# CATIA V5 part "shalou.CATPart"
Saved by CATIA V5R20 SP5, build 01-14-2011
Part number: Part8
Material "Smoked Glass": density 2190 kg/m3, Young's modulus 6.5e+10 Pa, Poisson ratio 0.161, thermal expansion 8e-05 1/K
Material "Smoked Glass": density 2190 kg/m3, Young's modulus 6.5e+10 Pa, Poisson ratio 0.161, thermal expansion 8e-05 1/K
Bounding box of the stored display mesh (mm): x -100 to 100, y -100 to 100, z 0 to 336
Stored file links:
  E:\180521217王瑞博\shalou.CATPart
  C:\Program Files\Dassault Systemes\B20\intel_a\startup\materials\Catalog.CATMaterial
  C:\Program Files\Dassault Systemes\B20\intel_a\startup\materials\blue_fabric_01.jpg
  C:\Program Files\Dassault Systemes\B20\intel_a\startup\materials\blue_env_512x512.jpg
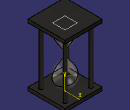
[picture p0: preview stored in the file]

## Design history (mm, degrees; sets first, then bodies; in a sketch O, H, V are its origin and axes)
Body1 (main body), material "Smoked Glass"
  Sketch1 on xy-plane, origin (0, 0, 0), H (1, 0, 0), V (0, 1, 0)
    line L1 (100, -100) -> (-100, -100)
    line L2 (-100, -100) -> (-100, 100)
    line L3 (-100, 100) -> (100, 100)
    line L4 (100, 100) -> (100, -100)
    length L4 = 200
    length L1 = 200
    horizontal: L1 H, L3 H
    vertical: L2 V, L4 V
  Pad1: profile Sketch1, direction (0, 0, 1), length 18
  Plane1: type Offset, RefPlane end face of Pad1, Offset 300, reversed
  Sketch2 on Plane1, origin (0, 0, 318), H (1, 0, 0), V (0, -1, 0)
    line L1 (100, -100) -> (-100, -100)
    line L2 (-100, -100) -> (-100, 100)
    line L3 (-100, 100) -> (100, 100)
    line L4 (100, 100) -> (100, -100)
    horizontal: L1 H, L3 H
    vertical: L2 V, L4 V
  Pad2: profile Sketch2, direction (0, 0, 1), length 18
  Sketch3 on xy-plane, origin (0, 0, 0), H (1, 0, 0), V (0, 1, 0)
    circle A1 centre (-70, -60) radius 10
    circle A2 centre (70, -60) radius 10
    circle A3 centre (70, 70) radius 10
    circle A4 centre (-70, 70) radius 10
  Pad3: profile Sketch3, direction (0, 0, 1), length 318
  Sketch4 on yz-plane, origin (0, 0, 0), H (0, 1, 0), V (0, 0, 1)
Body2, material "Smoked Glass"
  Sketch5 on zx-plane, origin (0, 0, 0), H (-1, 0, 0), V (0, 0, 1)
    spline S1 through (0, 315.0522) (40.2361, 297.9373) (32.3907, 230.5966) (1.9933, 177.936) (43.226, 106.1732) (41.2328, 39.1055) (0, 20.451)
    axis line L1 (0, 351.8152) -> (0, -13.8281)
    point P1 (0, 351.8152)
    coincidence: P1 V
    vertical: L1 V
  Shaft1: profile Sketch5, axis Sketch5.L1, angle 360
